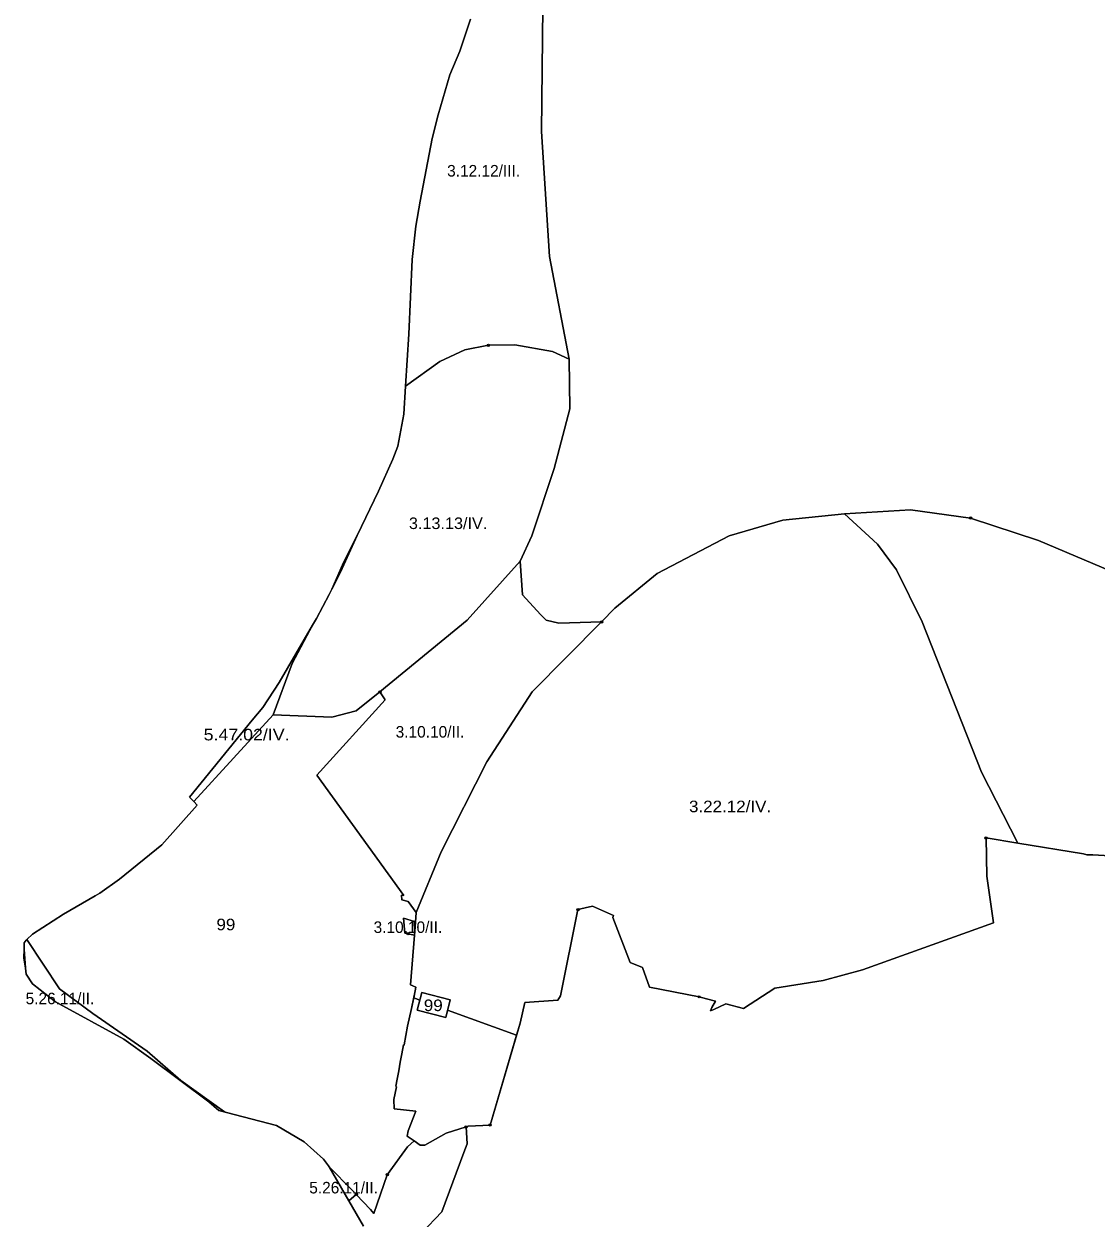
# Model space of a CAD drawing. Extents: x -650455 to -642254, y -1075222 to -1066610.
# Drawn here: x -649075 to -648146, y -1074176 to -1073142 of the extents above; entities that cross this region are included whole.
import ezdxf
from ezdxf.enums import TextEntityAlignment as Align

# ---------------------------------------------------------------- set-up
doc = ezdxf.new("R2010")
doc.units = 0
doc.header["$LTSCALE"] = 4
doc.header["$PDMODE"] = 32
doc.header["$PDSIZE"] = 2
for name, color, linetype, lineweight in [('1', 7, 'Continuous', 25), ('12', 7, 'Continuous', 13), ('13', 7, 'Continuous', 13), ('14', 7, 'Continuous', 13), ('16', 7, 'Continuous', 13)]:
    doc.layers.add(name, color=color, linetype=linetype, lineweight=lineweight)
doc.layers.add('2', color=7, linetype='Continuous')

msp = doc.modelspace()

# ---------------------------------------------------------------- linework, layer by layer
at = {"layer": '1'}
for points in [[(-648625, -1073100.5), (-648626.5, -1073235.5), (-648619.5, -1073343.5), (-648602.5, -1073432.5), (-648617, -1073426), (-648649.5, -1073420.001), (-648672.5, -1073420.5), (-648693, -1073424.5), (-648714.5, -1073434.501), (-648744.217, -1073455.79), (-648741.42, -1073410.767), (-648738.549, -1073346.144), (-648735.389, -1073317.422), (-648731.52, -1073295.605), (-648721.316, -1073241.598), (-648716.146, -1073220.918), (-648705.806, -1073186.453), (-648697.333, -1073165.774), (-648687.999, -1073138.202)], [(-648602, -1073475.501), (-648602.5, -1073432.5), (-648619.5, -1073343.5), (-648626.5, -1073235.5), (-648625, -1073100.5)], [(-648062.5, -1073646.001), (-648196, -1073589.501), (-648255, -1073570), (-648307, -1073563), (-648364, -1073566.5), (-648417.5, -1073572), (-648464, -1073585.501), (-648526.5, -1073618.001), (-648563, -1073648), (-648574.5, -1073660), (-648611.5, -1073661), (-648622.5, -1073658.501), (-648627.5, -1073653.501), (-648643, -1073636.5), (-648645, -1073607.5), (-648635, -1073585.501), (-648615.5, -1073527), (-648602, -1073475.501)], [(-648752.57, -1074061.851), (-648751.57, -1074055.821), (-648750.22, -1074048.451), (-648748.85, -1074041.09), (-648747.5, -1074033.741), (-648746.05, -1074026.171), (-648745.45, -1074026.31), (-648745.41, -1074026.111), (-648742.61, -1074010.011), (-648739.19, -1073994.71), (-648735.92, -1073979.321), (-648735.23, -1073976.071), (-648740, -1073974.001), (-648736.58, -1073931.24), (-648736.321, -1073928.012), (-648735, -1073911.5), (-648713.5, -1073859), (-648674, -1073781), (-648634.5, -1073720.5), (-648574.5, -1073660), (-648563, -1073648), (-648526.5, -1073618.001), (-648464, -1073585.501), (-648417.5, -1073572), (-648364, -1073566.5), (-648335.5, -1073592.501), (-648319, -1073615), (-648297, -1073660), (-648245.5, -1073790), (-648214, -1073851.501)], [(-648110, -1073864.001), (-648149.105, -1073861.45), (-648149.15, -1073861.451), (-648154.13, -1073861.481), (-648157.04, -1073860.831), (-648214, -1073851.501), (-648245.5, -1073790), (-648297, -1073660), (-648319, -1073615), (-648335.5, -1073592.501), (-648364, -1073566.5), (-648307, -1073563), (-648255, -1073570), (-648196, -1073589.501), (-648062.5, -1073646.001)], [(-648901, -1074084.001), (-648939, -1074057), (-648968, -1074031.501), (-649015, -1073999.001), (-649044, -1073977.501), (-649072.294, -1073934.835), (-649067.407, -1073930.333), (-649040.497, -1073913.053), (-649013.146, -1073897.066), (-649009.16, -1073894.737), (-648991.907, -1073882.759), (-648955.288, -1073852.817), (-648924.795, -1073818.448), (-648927.621, -1073815.481), (-648859, -1073740.5), (-648808, -1073742.501), (-648787, -1073737), (-648766.5, -1073720.5), (-648762, -1073727.501), (-648821, -1073792.501), (-648745.64, -1073896.781), (-648747.8, -1073896.441), (-648747.45, -1073900.56), (-648741.97, -1073901.861), (-648735, -1073911.5)], [(-648214, -1073851.501), (-648241.5, -1073847), (-648241, -1073880.001), (-648235, -1073920.501), (-648348.5, -1073961.001), (-648382.5, -1073970.501), (-648424.5, -1073977.001), (-648451.5, -1073994.501), (-648466.848, -1073990.514), (-648477.31, -1073995.351), (-648480.31, -1073996.631), (-648478.94, -1073993.79), (-648475.77, -1073988.2), (-648483.64, -1073986.15), (-648490, -1073984.5), (-648533, -1073976), (-648539.18, -1073959.08), (-648549.76, -1073954.86), (-648564.75, -1073915.911), (-648564.13, -1073914.061), (-648582.5, -1073906.001), (-648595, -1073909.001), (-648610, -1073983.5), (-648612.5, -1073987.5), (-648641, -1073989.501), (-648644.975, -1074007.201), (-648671, -1074095.501), (-648690, -1074096.5), (-648691.81, -1074097.071), (-648709, -1074102.501), (-648727.5, -1074113), (-648731.5, -1074113), (-648736.831, -1074109.292), (-648743, -1074105), (-648742, -1074100.5), (-648735.5, -1074083.501), (-648754, -1074081.5), (-648754.5, -1074073.5), (-648752.09, -1074062.33), (-648752.57, -1074061.851)], [(-648690.92, -1074111.641), (-648691.81, -1074097.071), (-648690, -1074096.5), (-648671, -1074095.501), (-648644.975, -1074007.201), (-648641, -1073989.501), (-648612.5, -1073987.5), (-648610, -1073983.5), (-648595, -1073909.001), (-648582.5, -1073906.001), (-648564.13, -1073914.061), (-648564.75, -1073915.911), (-648549.76, -1073954.86), (-648539.18, -1073959.08), (-648533, -1073976), (-648490, -1073984.5), (-648483.64, -1073986.15), (-648475.77, -1073988.2), (-648478.94, -1073993.79), (-648480.31, -1073996.631), (-648477.31, -1073995.351), (-648466.848, -1073990.514), (-648451.5, -1073994.501), (-648424.5, -1073977.001), (-648382.5, -1073970.501), (-648348.5, -1073961.001), (-648235, -1073920.501), (-648241, -1073880.001), (-648241.5, -1073847), (-648214, -1073851.501), (-648157.04, -1073860.831), (-648154.13, -1073861.481), (-648149.15, -1073861.451), (-648149.105, -1073861.45), (-648110, -1073864.001)], [(-648735, -1073911.5), (-648736.321, -1073928.012), (-648736.6, -1073919.261), (-648746.08, -1073916.36), (-648744.97, -1073929.301), (-648742.17, -1073929.951), (-648736.58, -1073931.24), (-648740, -1073974.001), (-648735.23, -1073976.071), (-648735.92, -1073979.321), (-648739.19, -1073994.71), (-648742.61, -1074010.011), (-648745.41, -1074026.111), (-648745.45, -1074026.31), (-648746.05, -1074026.171), (-648747.5, -1074033.741), (-648748.85, -1074041.09), (-648750.22, -1074048.451), (-648751.57, -1074055.821), (-648752.57, -1074061.851), (-648752.09, -1074062.33), (-648754.5, -1074073.5), (-648754, -1074081.5), (-648735.5, -1074083.501), (-648742, -1074100.5), (-648743, -1074105), (-648736.831, -1074109.292), (-648742.6, -1074114.47), (-648760.17, -1074138.5), (-648771.8, -1074172.011), (-648774.5, -1074168.501), (-648787, -1074155.501), (-648790.527, -1074151.91), (-648810.451, -1074131.626), (-648810.9, -1074130.849), (-648815.201, -1074125.143), (-648832.102, -1074109.996), (-648856.045, -1074095.905), (-648899.457, -1074084.507), (-648901, -1074084.001)], [(-648780.692, -1074183.167), (-648793.41, -1074161.141), (-648787, -1074155.501), (-648774.5, -1074168.501), (-648771.8, -1074172.011), (-648760.17, -1074138.5), (-648742.6, -1074114.47), (-648736.831, -1074109.292), (-648731.5, -1074113), (-648727.5, -1074113), (-648709, -1074102.501), (-648691.81, -1074097.071), (-648690.92, -1074111.641), (-648693.71, -1074119.171), (-648712.77, -1074170.511), (-648730.34, -1074189.22)], [(-648730.34, -1074189.22), (-648712.77, -1074170.511), (-648693.71, -1074119.171), (-648690.92, -1074111.641)]]:
    msp.add_lwpolyline(points, dxfattribs=at)
for points in [[(-648602.5, -1073432.5), (-648602, -1073475.501), (-648615.5, -1073527), (-648635, -1073585.501), (-648645, -1073607.5), (-648691, -1073658.501), (-648766.5, -1073720.5), (-648787, -1073737), (-648808, -1073742.501), (-648859, -1073740.5), (-648842.5, -1073696), (-648824.895, -1073662.886), (-648821.41, -1073656.907), (-648810.352, -1073636.229), (-648808.214, -1073631.51), (-648800.5, -1073617.001), (-648786.307, -1073585.006), (-648767.557, -1073546.618), (-648755.207, -1073519.046), (-648751.042, -1073507.7), (-648745.729, -1073480.128), (-648744.217, -1073455.79), (-648714.5, -1073434.501), (-648693, -1073424.5), (-648672.5, -1073420.5), (-648649.5, -1073420.001), (-648617, -1073426)], [(-648800.5, -1073617.001), (-648808.214, -1073631.51), (-648797.858, -1073608.656), (-648786.307, -1073585.006)], [(-648574.5, -1073660), (-648634.5, -1073720.5), (-648674, -1073781), (-648713.5, -1073859), (-648735, -1073911.5), (-648741.97, -1073901.861), (-648747.45, -1073900.56), (-648747.8, -1073896.441), (-648745.64, -1073896.781), (-648821, -1073792.501), (-648762, -1073727.501), (-648766.5, -1073720.5), (-648691, -1073658.501), (-648645, -1073607.5), (-648643, -1073636.5), (-648627.5, -1073653.501), (-648622.5, -1073658.501), (-648611.5, -1073661)], [(-648859, -1073740.5), (-648927.621, -1073815.481), (-648931.394, -1073811.522), (-648876.987, -1073745.13), (-648867.83, -1073734.107), (-648853.721, -1073712.339), (-648824.895, -1073662.886), (-648842.5, -1073696)], [(-648736.321, -1073928.012), (-648736.58, -1073931.24), (-648742.17, -1073929.951), (-648744.97, -1073929.301), (-648746.08, -1073916.36), (-648736.6, -1073919.261)], [(-648901, -1074084.001), (-648899.457, -1074084.507), (-648905.982, -1074082.794), (-648914.505, -1074075.443), (-648964.729, -1074037.751), (-648988.179, -1074021.285), (-649047.332, -1073988.878), (-649067.402, -1073973.379), (-649072.684, -1073964.925), (-649073.486, -1073959.574), (-649074.593, -1073943.317), (-649074.444, -1073937.802), (-649072.864, -1073935.36), (-649072.294, -1073934.835), (-649044, -1073977.501), (-649015, -1073999.001), (-648968, -1074031.501), (-648939, -1074057)], [(-649074.593, -1073943.317), (-649073.486, -1073959.574), (-649074.797, -1073950.834)], [(-648705.68, -1073987.171), (-648709.33, -1074002.301), (-648734.08, -1073996.051), (-648730.17, -1073980.81)], [(-648705.68, -1073987.171), (-648730.17, -1073980.81), (-648734.08, -1073996.051), (-648709.33, -1074002.301)], [(-648787, -1074155.501), (-648793.41, -1074161.141), (-648810.451, -1074131.626), (-648790.527, -1074151.91)]]:
    msp.add_lwpolyline(points, close=True, dxfattribs=at)
at = {"layer": '12'}
msp.add_line((-648793.41, -1074161.141), (-648787, -1074155.501), dxfattribs=at)
for points in [[(-648741.97, -1073901.861), (-648735, -1073911.5), (-648713.5, -1073859), (-648674, -1073781), (-648634.5, -1073720.5), (-648574.5, -1073660), (-648611.5, -1073661), (-648622.5, -1073658.501), (-648627.5, -1073653.501), (-648643, -1073636.5), (-648645, -1073607.5), (-648691, -1073658.501), (-648766.5, -1073720.5), (-648762, -1073727.501), (-648821, -1073792.501), (-648745.64, -1073896.781), (-648747.8, -1073896.441), (-648747.45, -1073900.56)], [(-648742.17, -1073929.951), (-648736.58, -1073931.24), (-648736.321, -1073928.012), (-648736.6, -1073919.261), (-648746.08, -1073916.36), (-648744.97, -1073929.301)], [(-649047.332, -1073988.878), (-648988.179, -1074021.285), (-648964.729, -1074037.751), (-648914.505, -1074075.443), (-648905.982, -1074082.794), (-648899.457, -1074084.507), (-648901, -1074084.001), (-648939, -1074057), (-648968, -1074031.501), (-649015, -1073999.001), (-649044, -1073977.501), (-649072.294, -1073934.835), (-649072.864, -1073935.36), (-649074.444, -1073937.802), (-649074.593, -1073943.317), (-649073.486, -1073959.574), (-649072.684, -1073964.925), (-649067.402, -1073973.379)]]:
    msp.add_lwpolyline(points, close=True, dxfattribs=at)
for points in [[(-648730.34, -1074189.22), (-648712.77, -1074170.511), (-648693.71, -1074119.171), (-648690.92, -1074111.641), (-648691.81, -1074097.071), (-648709, -1074102.501), (-648727.5, -1074113), (-648731.5, -1074113), (-648736.831, -1074109.292), (-648742.6, -1074114.47), (-648760.17, -1074138.5), (-648771.8, -1074172.011), (-648774.5, -1074168.501), (-648787, -1074155.501), (-648793.41, -1074161.141), (-648780.692, -1074183.167)], [(-648787, -1074155.501), (-648790.527, -1074151.91), (-648810.451, -1074131.626), (-648793.41, -1074161.141)]]:
    msp.add_lwpolyline(points, dxfattribs=at)
for p in [(-648742.17, -1073929.951), (-648787, -1074155.501)]:
    msp.add_point(p, dxfattribs=at)
at = {"layer": '13'}
for points in [[(-648687.999, -1073138.202), (-648697.333, -1073165.774), (-648705.806, -1073186.453), (-648716.146, -1073220.918), (-648721.316, -1073241.598), (-648731.52, -1073295.605), (-648735.389, -1073317.422), (-648738.549, -1073346.144), (-648741.42, -1073410.767), (-648744.217, -1073455.79), (-648714.5, -1073434.501), (-648693, -1073424.5), (-648672.5, -1073420.5), (-648649.5, -1073420.001), (-648617, -1073426), (-648602.5, -1073432.5), (-648619.5, -1073343.5), (-648626.5, -1073235.5), (-648625, -1073100.5)], [(-648625, -1073100.5), (-648626.5, -1073235.5), (-648619.5, -1073343.5), (-648602.5, -1073432.5), (-648602, -1073475.501), (-648615.5, -1073527), (-648635, -1073585.501), (-648645, -1073607.5), (-648643, -1073636.5), (-648627.5, -1073653.501), (-648622.5, -1073658.501), (-648611.5, -1073661), (-648574.5, -1073660)], [(-648574.5, -1073660), (-648563, -1073648), (-648526.5, -1073618.001), (-648464, -1073585.501), (-648417.5, -1073572), (-648364, -1073566.5), (-648307, -1073563), (-648255, -1073570)], [(-648062.5, -1073646.001), (-648196, -1073589.501), (-648255, -1073570), (-648307, -1073563), (-648364, -1073566.5), (-648335.5, -1073592.501), (-648319, -1073615), (-648297, -1073660), (-648245.5, -1073790), (-648214, -1073851.501), (-648157.04, -1073860.831), (-648154.13, -1073861.481), (-648149.15, -1073861.451), (-648149.105, -1073861.45), (-648110, -1073864.001)], [(-648255, -1073570), (-648196, -1073589.501), (-648062.5, -1073646.001), (-647997.5, -1073679.5), (-647977, -1073687.001), (-647941, -1073695.001), (-647920, -1073695.5), (-647891.5, -1073692.5), (-647875, -1073690.501), (-647823.5, -1073666.001), (-647745, -1073642.501), (-647710, -1073641.001), (-647684, -1073648), (-647654.5, -1073672), (-647648.56, -1073674.85), (-647570, -1073712.5), (-647585, -1073748.5)]]:
    msp.add_lwpolyline(points, dxfattribs=at)
for p in [(-648672.5, -1073420.5), (-648255, -1073570), (-648574.5, -1073660)]:
    msp.add_point(p, dxfattribs=at)
at = {"layer": '14'}
for points in [[(-648766.5, -1073720.5), (-648691, -1073658.501), (-648645, -1073607.5), (-648635, -1073585.501), (-648615.5, -1073527), (-648602, -1073475.501), (-648602.5, -1073432.5), (-648617, -1073426), (-648649.5, -1073420.001), (-648672.5, -1073420.5), (-648693, -1073424.5), (-648714.5, -1073434.501), (-648744.217, -1073455.79), (-648745.729, -1073480.128), (-648751.042, -1073507.7), (-648755.207, -1073519.046), (-648767.557, -1073546.618), (-648786.307, -1073585.006), (-648800.5, -1073617.001), (-648808.214, -1073631.51), (-648810.352, -1073636.229), (-648821.41, -1073656.907), (-648824.895, -1073662.886), (-648842.5, -1073696), (-648859, -1073740.5), (-648808, -1073742.501), (-648787, -1073737)], [(-648859, -1073740.5), (-648842.5, -1073696), (-648824.895, -1073662.886), (-648853.721, -1073712.339), (-648867.83, -1073734.107), (-648876.987, -1073745.13), (-648931.394, -1073811.522), (-648927.621, -1073815.481)]]:
    msp.add_lwpolyline(points, close=True, dxfattribs=at)
for points in [[(-648241.5, -1073847), (-648214, -1073851.501), (-648245.5, -1073790), (-648297, -1073660), (-648319, -1073615), (-648335.5, -1073592.501), (-648364, -1073566.5), (-648417.5, -1073572), (-648464, -1073585.501), (-648526.5, -1073618.001), (-648563, -1073648), (-648574.5, -1073660), (-648634.5, -1073720.5), (-648674, -1073781), (-648713.5, -1073859), (-648735, -1073911.5), (-648736.321, -1073928.012), (-648736.58, -1073931.24), (-648740, -1073974.001), (-648735.23, -1073976.071), (-648735.92, -1073979.321), (-648737.229, -1073985.48), (-648731.866, -1073987.422), (-648730.17, -1073980.81), (-648705.68, -1073987.171)], [(-648490, -1073984.5), (-648483.64, -1073986.15), (-648475.77, -1073988.2), (-648478.94, -1073993.79), (-648480.31, -1073996.631), (-648477.31, -1073995.351), (-648466.848, -1073990.514), (-648451.5, -1073994.501), (-648424.5, -1073977.001), (-648382.5, -1073970.501), (-648348.5, -1073961.001), (-648235, -1073920.501), (-648241, -1073880.001), (-648241.5, -1073847)], [(-648705.68, -1073987.171), (-648707.84, -1073996.123), (-648648.087, -1074017.761), (-648644.975, -1074007.201), (-648641, -1073989.501), (-648612.5, -1073987.5), (-648610, -1073983.5), (-648595, -1073909.001), (-648582.5, -1073906.001), (-648564.13, -1073914.061), (-648564.75, -1073915.911), (-648549.76, -1073954.86), (-648539.18, -1073959.08), (-648533, -1073976), (-648490, -1073984.5)], [(-648671, -1074095.501), (-648648.087, -1074017.761), (-648707.84, -1073996.123), (-648709.33, -1074002.301), (-648734.08, -1073996.051), (-648731.866, -1073987.422), (-648737.229, -1073985.48), (-648739.19, -1073994.71), (-648742.61, -1074010.011), (-648745.41, -1074026.111), (-648745.45, -1074026.31), (-648746.05, -1074026.171), (-648747.5, -1074033.741), (-648748.85, -1074041.09), (-648750.22, -1074048.451), (-648751.57, -1074055.821), (-648752.57, -1074061.851), (-648752.09, -1074062.33), (-648754.5, -1074073.5), (-648754, -1074081.5), (-648735.5, -1074083.501), (-648742, -1074100.5), (-648743, -1074105), (-648736.831, -1074109.292), (-648731.5, -1074113), (-648727.5, -1074113), (-648709, -1074102.501), (-648691.81, -1074097.071)], [(-648691.81, -1074097.071), (-648690, -1074096.5), (-648671, -1074095.501)]]:
    msp.add_lwpolyline(points, dxfattribs=at)
for p in [(-648766.5, -1073720.5), (-648241.5, -1073847), (-648490, -1073984.5), (-648671, -1074095.501)]:
    msp.add_point(p, dxfattribs=at)
at = {"layer": '16'}
for points in [[(-648760.17, -1074138.5), (-648742.6, -1074114.47), (-648736.831, -1074109.292), (-648743, -1074105), (-648742, -1074100.5), (-648735.5, -1074083.501), (-648754, -1074081.5), (-648754.5, -1074073.5), (-648752.09, -1074062.33), (-648752.57, -1074061.851), (-648751.57, -1074055.821), (-648750.22, -1074048.451), (-648748.85, -1074041.09), (-648747.5, -1074033.741), (-648746.05, -1074026.171), (-648745.45, -1074026.31), (-648745.41, -1074026.111), (-648742.61, -1074010.011), (-648739.19, -1073994.71), (-648739.185, -1073994.689), (-648737.229, -1073985.48), (-648735.92, -1073979.321), (-648735.23, -1073976.071), (-648740, -1073974.001), (-648736.58, -1073931.24), (-648742.17, -1073929.951), (-648744.97, -1073929.301), (-648746.08, -1073916.36), (-648736.6, -1073919.261), (-648736.321, -1073928.012), (-648735, -1073911.5), (-648741.97, -1073901.861), (-648747.45, -1073900.56), (-648747.8, -1073896.441), (-648745.64, -1073896.781), (-648821, -1073792.501), (-648762, -1073727.501), (-648766.5, -1073720.5), (-648787, -1073737), (-648808, -1073742.501)], [(-648808, -1073742.501), (-648859, -1073740.5), (-648927.621, -1073815.481), (-648924.795, -1073818.448), (-648955.288, -1073852.817), (-648991.907, -1073882.759), (-649009.16, -1073894.737), (-649013.146, -1073897.066), (-649040.497, -1073913.053), (-649067.407, -1073930.333), (-649072.294, -1073934.835), (-649044, -1073977.501), (-649015, -1073999.001), (-648968, -1074031.501), (-648939, -1074057), (-648901, -1074084.001), (-648899.457, -1074084.507), (-648856.045, -1074095.905)], [(-648241.5, -1073847), (-648241, -1073880.001), (-648235, -1073920.501), (-648348.5, -1073961.001), (-648382.5, -1073970.501), (-648424.5, -1073977.001), (-648451.5, -1073994.501), (-648466.848, -1073990.514), (-648477.31, -1073995.351), (-648480.31, -1073996.631), (-648478.94, -1073993.79), (-648475.77, -1073988.2), (-648483.64, -1073986.15), (-648490, -1073984.5), (-648533, -1073976), (-648539.18, -1073959.08), (-648549.76, -1073954.86), (-648564.75, -1073915.911), (-648564.13, -1073914.061), (-648582.5, -1073906.001), (-648595, -1073909.001)], [(-648110, -1073864.001), (-648149.105, -1073861.45), (-648149.15, -1073861.451), (-648154.13, -1073861.481), (-648157.04, -1073860.831), (-648214, -1073851.501), (-648241.5, -1073847)], [(-648595, -1073909.001), (-648610, -1073983.5), (-648612.5, -1073987.5), (-648641, -1073989.501), (-648644.975, -1074007.201), (-648648.087, -1074017.761), (-648670.931, -1074095.265), (-648671, -1074095.501), (-648690, -1074096.5), (-648691.81, -1074097.071)], [(-648856.045, -1074095.905), (-648832.102, -1074109.996), (-648815.201, -1074125.143), (-648810.9, -1074130.849), (-648810.451, -1074131.626), (-648790.527, -1074151.91), (-648787, -1074155.501), (-648774.5, -1074168.501), (-648771.8, -1074172.011), (-648760.17, -1074138.5)], [(-648691.81, -1074097.071), (-648690.92, -1074111.641), (-648693.71, -1074119.171), (-648712.77, -1074170.511), (-648730.34, -1074189.22), (-648748.74, -1074206.61), (-648778.97, -1074232.99), (-648829.66, -1074270.99), (-648848.34, -1074286.15), (-648847.75, -1074276.773), (-648846.06, -1074249.88), (-648844.4, -1074227.801), (-648844.05, -1074223.243), (-648833.11, -1074225.201), (-648806.55, -1074212.621), (-648795.65, -1074205.351), (-648784.8, -1074195.26), (-648778.42, -1074187.097)]]:
    msp.add_lwpolyline(points, dxfattribs=at)
msp.add_lwpolyline([(-648709.33, -1074002.301), (-648705.68, -1073987.171), (-648730.17, -1073980.81), (-648734.08, -1073996.051)], close=True, dxfattribs=at)
for p in [(-648595, -1073909.001), (-648691.81, -1074097.071), (-648760.17, -1074138.5)]:
    msp.add_point(p, dxfattribs=at)

# ---------------------------------------------------------------- texts
at = {"layer": '2'}
for s, p in [('3.12.12/III.', (-648676.665, -1073274.395)), ('3.10.10/II.', (-648723.083, -1073760.098)), ('3.10.10/II.', (-648742.201, -1073929.202)), ('5.26.11/II.', (-649043.547, -1073990.91)), ('5.26.11/II.', (-648797.931, -1074154.685))]:
    msp.add_text(s, height=10, dxfattribs=at).set_placement(p, align=Align.CENTER)
for s, width, p in [('3.13.13/IV.', 1.05, (-648707.405, -1073579.546)), ('5.47.02/IV.', 1.15, (-648881.907, -1073762.501)), ('3.22.12/IV.', 1.1, (-648463.217, -1073824.682)), ('99', 1.1, (-648899.843, -1073926.88)), ('99', 1.1, (-648720.26, -1073996.851))]:
    msp.add_text(s, height=10, dxfattribs=dict(at, width=width)).set_placement(p, align=Align.CENTER)

doc.saveas('drawing.dxf')
